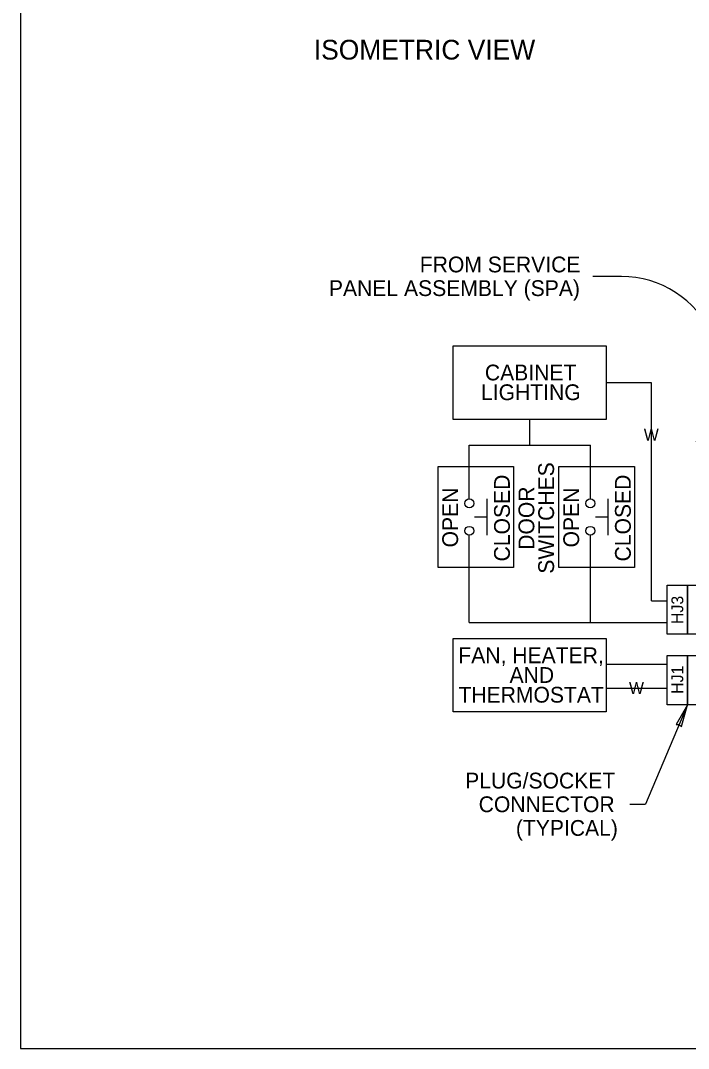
# Model space of a CAD drawing. Extents: x 99862 to 103680, y 99470 to 102076.
# Drawn here: x 99862 to 100539, y 100000 to 101041 of the extents above; entities that cross this region are included whole.
import ezdxf

# ---------------------------------------------------------------- set-up
doc = ezdxf.new("R2010")
doc.units = 0
for name, color, linetype in [('Level 1', 7, 'Continuous'), ('Level 15', 7, 'Continuous'), ('Level 20', 7, 'Continuous'), ('Level 26', 7, 'Continuous'), ('Level 60', 7, 'Continuous')]:
    doc.layers.add(name, color=color, linetype=linetype)

msp = doc.modelspace()

# ---------------------------------------------------------------- linework, layer by layer
at = {"layer": 'Level 1'}
msp.add_lwpolyline([(99862, 99999.5), (103151, 99999.5), (103151, 102075.5), (99862, 102075.5)], close=True, dxfattribs=at)
at = {"layer": 'Level 15'}
for p, q in [((100442.2, 100782.1), (100471.2, 100782.1)), ((100538.1, 100347.9), (100495.6, 100247)), ((100479.6, 100247), (100495.6, 100247))]:
    msp.add_line(p, q, dxfattribs=at)
msp.add_lwpolyline([(100538.1, 100347.9), (100526.5, 100328), (100529.7, 100327.9), (100532, 100325.7)], close=True, dxfattribs=at)
msp.add_arc((100471.2, 100681.1), 100.9, 318.5415, 90, dxfattribs=at)
at = {"layer": 'Level 26'}
for p, q in [((100501.6, 100674.3), (100455.7, 100674.3)), ((100501.6, 100453.3), (100501.6, 100674.3)), ((100378.2, 100610.8), (100378.2, 100637.1)), ((100316.9, 100556.5), (100316.9, 100610.8)), ((100316.9, 100610.8), (100439.6, 100610.8)), ((100439.6, 100556.5), (100439.6, 100610.8)), ((100334.7, 100556.5), (100334.7, 100519.7)), ((100457.4, 100556.5), (100457.4, 100519.7)), ((100334.7, 100538.1), (100322.1, 100538.1)), ((100457.4, 100538.1), (100444.8, 100538.1)), ((100316.9, 100431.1), (100316.9, 100519.7)), ((100439.6, 100431.1), (100439.6, 100519.7)), ((100501.6, 100453.3), (100517.5, 100453.3)), ((100316.9, 100431.1), (100517.5, 100431.1)), ((100455.7, 100389), (100517.5, 100389)), ((100455.7, 100364.8), (100517.5, 100364.8))]:
    msp.add_line(p, q, dxfattribs=at)
for points in [[(100455.7, 100637.1), (100300.7, 100637.1), (100300.7, 100711.6), (100455.7, 100711.6)], [(100285.2, 100589.3), (100361.8, 100589.3), (100361.8, 100486.8), (100285.2, 100486.8)], [(100407.8, 100589.3), (100484.5, 100589.3), (100484.5, 100486.8), (100407.8, 100486.8)], [(100517.5, 100469.2), (100538.1, 100469.2), (100538.1, 100419.3), (100517.5, 100419.3)], [(100538.1, 100469.2), (100558.7, 100469.2), (100558.7, 100419.3), (100538.1, 100419.3)], [(100455.7, 100340.6), (100300.7, 100340.6), (100300.7, 100415), (100455.7, 100415)], [(100517.5, 100397.8), (100538.1, 100397.8), (100538.1, 100347.9), (100517.5, 100347.9)], [(100538.1, 100397.8), (100558.7, 100397.8), (100558.7, 100347.9), (100538.1, 100347.9)]]:
    msp.add_lwpolyline(points, close=True, dxfattribs=at)
for centre in [(100316.9, 100552), (100439.6, 100552), (100316.9, 100524.2), (100439.6, 100524.2)]:
    msp.add_circle(centre, 4.47, dxfattribs=at)
at = {"layer": 'Level 60'}
msp.add_line((99862, 99999.5), (99862, 99999.5), dxfattribs=at)

# ---------------------------------------------------------------- texts
at = {"layer": 'Level 20'}
for s, height, p in [('ISOMETRIC VIEW', 20, (100159.3, 101001.8)), ('FROM SERVICE', 16, (100266.7, 100786.1)), ('PANEL ASSEMBLY (SPA)', 16, (100174.6, 100762.1)), ('CABINET', 16, (100332.7, 100676.6)), ('LIGHTING', 16, (100328.8, 100656.6)), ('W', 12, (100493.8, 100615.6)), ('FAN, HEATER,', 16, (100305.8, 100390)), ('AND ', 16, (100357.7, 100370)), ('W', 12, (100478.8, 100358.8)), ('THERMOSTAT', 16, (100305.9, 100350)), ('PLUG/SOCKET', 16, (100312.7, 100263)), ('CONNECTOR', 16, (100326.4, 100239)), ('(TYPICAL)', 16, (100364.1, 100215))]:
    msp.add_text(s, height=height, dxfattribs=at).set_placement(p)
for s, height, p in [('SWITCHES', 16, (100402.8, 100480.7)), ('CLOSED', 16, (100358, 100493.1)), ('CLOSED', 16, (100480.6, 100493.1)), ('DOOR', 16, (100382.8, 100504.9)), ('OPEN', 16, (100305.5, 100507.3)), ('OPEN', 16, (100428.2, 100507.3)), ('HJ3', 12, (100533.8, 100429.7)), ('HJ1', 12, (100533.8, 100358.9))]:
    msp.add_text(s, height=height, rotation=90, dxfattribs=at).set_placement(p)

doc.saveas('drawing.dxf')
